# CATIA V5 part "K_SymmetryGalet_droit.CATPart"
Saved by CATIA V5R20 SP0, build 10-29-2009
Part number: Symmetry of Galet_droit
Bounding box of the stored display mesh (mm): x 0 to 17.955, y -11.571 to 11.571, z -11.571 to 11.571
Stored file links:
  G:\Khaled_CFAO_2011\SIL\SIL_GR2\zthiebault\Khaled\CAD_ThinkMOTION\K_SymmetryGalet_droit.CATPart
  G:\Khaled_CFAO_2011\SIL\SIL_GR2\zthiebault\Khaled\CAD_ThinkMOTION\K_Galet_droit.CATPart
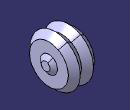
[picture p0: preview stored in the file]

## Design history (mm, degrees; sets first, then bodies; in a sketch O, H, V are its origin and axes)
Body1 (main body)
  Body2 "Corps du corps principal d'origine"
    Solid1: linked copy from another document
  Assemble1: tool Body2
